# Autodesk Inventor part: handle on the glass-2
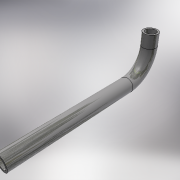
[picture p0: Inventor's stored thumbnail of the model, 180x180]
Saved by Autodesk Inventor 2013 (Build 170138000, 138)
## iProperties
Shininess: 64.0
Length Units: 11269
Angle Units: 11279
Time Units: 11290
Mass Units: 11283
Length Display Precision: 3
Angle Display Precision: 2
Compacted: True
Part Number: handle on the glass-2
Document SubType Name: Modeling
Created: 2005-02
Material: Stainless Steel, 440C
Designer: =<Author>
Manufacturer: Standard
Standards Organization: Custom
Description: =<Part Number>
Density: 7.75 g/cm^3
Mass: 132.339 g
Surface Area: 172.52 cm^2
Volume: 17.076 cm^3
Density: 0.0
Volumn: 0.0
Area: 0.0
PropertySet Name: Model Information
Control State: 0
Master: False
Checked Out: False
Checked Out Date: 2008-10-15
Last Check In Date: 2008-10-15
Author: PVitaliy
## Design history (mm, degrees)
feature "Сдвиг1" dims "d6" = 0
body "Solid1"
sketch "Эскиз1"
  geometry: C1 r 8 at (0, 0); C2 r 6 at (0, 0)
  constraints: 2 centre point, 1 coincident, 1 other
  dimensions: "d0" = 16 diameter of C1; "d1" = 12 diameter of C2
sketch "Эскиз2"
  geometry: L1 (0, 0)-(0, -14); L2 (-30, -44)-(-163, -44); A1 r 30 centre (-30, -14) between (-30, -44) and (0, -14); 1 further point
  constraints: 4 end point, 2 point on circle, 2 point on line, 2 tangent, 1 centre point, 1 perpendicular, 1 vertical
  dimensions: "d3" = 44 distance of L1.start point (0, -44); "d5" = 30 radius of A1; "d7" = 163 distance from line of L2.end L1
